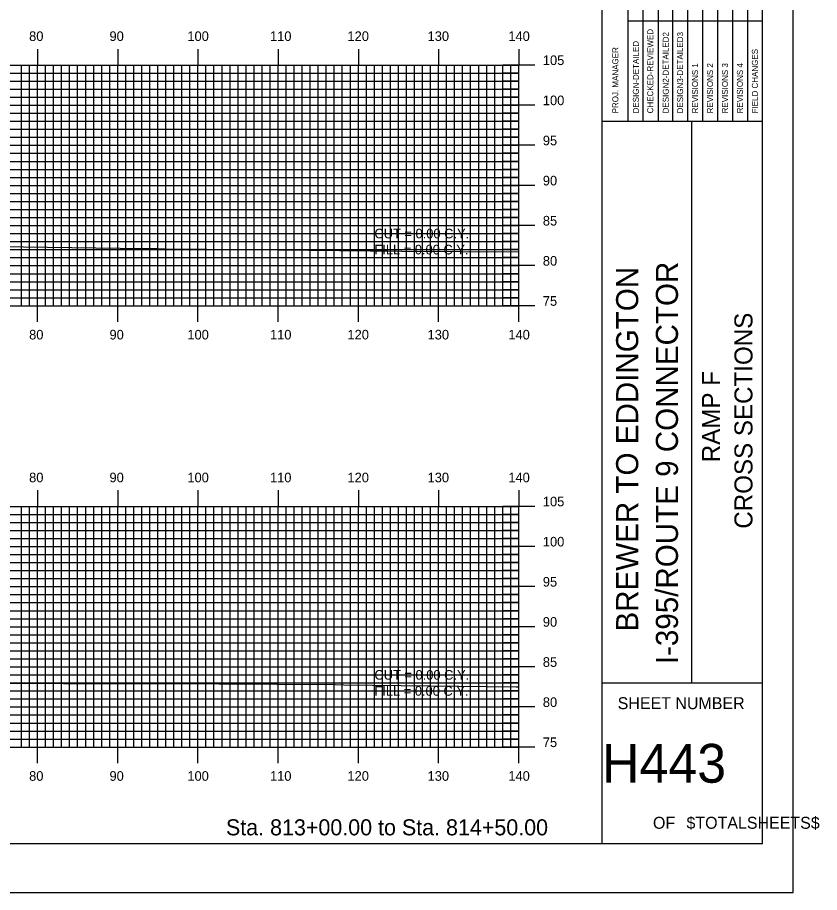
# Model space of a CAD drawing. Extents: x 2453 to 2796, y -1658 to -1438.
# Drawn here: x 2696.2 to 2796.2, y -1657.7 to -1548.7 of the extents above; entities that cross this region are included whole.
import ezdxf

# ---------------------------------------------------------------- set-up
doc = ezdxf.new("R2010")
doc.units = 0
for name, color, linetype in [('BORDER', 7, 'Continuous'), ('D_Text_Standard', 7, 'Continuous'), ('H_V ANNOTATION', 7, 'Continuous'), ('MAJOR', 7, 'Continuous'), ('MINOR', 7, 'Continuous'), ('PLOT BOUNDARY', 7, 'Continuous'), ('S_Roadway_Centerline', 7, 'Continuous')]:
    doc.layers.add(name, color=color, linetype=linetype)

msp = doc.modelspace()

# ---------------------------------------------------------------- linework, layer by layer
at = {"layer": 'BORDER'}
for p, q in [((2769.1, -1651.6), (2769.1, -1441.6)), ((2769.1, -1561.6), (2789.1, -1561.6)), ((2780.28, -1631.6), (2780.28, -1561.6)), ((2769.1, -1631.6), (2789.1, -1631.6))]:
    msp.add_line(p, q, dxfattribs=at)
msp.add_lwpolyline([(2469.1, -1651.6), (2789.1, -1651.6), (2789.1, -1441.6), (2469.1, -1441.6)], close=True, dxfattribs=at)
for points in [[(2774.19, -1561.59), (2774.19, -1526.6)], [(2776.06, -1526.6), (2776.06, -1561.59)], [(2777.92, -1561.59), (2777.92, -1526.6)], [(2779.78, -1561.59), (2779.78, -1526.6)], [(2781.65, -1561.59), (2781.65, -1526.6)], [(2783.51, -1561.59), (2783.51, -1526.6)], [(2785.37, -1561.59), (2785.37, -1526.6)], [(2787.24, -1561.59), (2787.24, -1526.6)], [(2772.33, -1561.59), (2772.33, -1528.01)], [(2772.33, -1549.1), (2789.1, -1549.1)]]:
    msp.add_lwpolyline(points, dxfattribs=at)
at = {"layer": 'MAJOR'}
for p, q in [((2698.7, -1552.6), (2698.7, -1554.6)), ((2708.7, -1552.6), (2708.7, -1554.6)), ((2718.7, -1552.6), (2718.7, -1554.6)), ((2728.7, -1552.6), (2728.7, -1554.6)), ((2738.7, -1552.6), (2738.7, -1554.6)), ((2748.7, -1552.6), (2748.7, -1554.6)), ((2758.7, -1552.6), (2758.7, -1554.6)), ((2478.7, -1554.6), (2758.7, -1554.6)), ((2478.7, -1554.6), (2758.7, -1554.6)), ((2698.7, -1584.6), (2698.7, -1554.6)), ((2708.7, -1584.6), (2708.7, -1554.6)), ((2718.7, -1584.6), (2718.7, -1554.6)), ((2728.7, -1584.6), (2728.7, -1554.6)), ((2738.7, -1584.6), (2738.7, -1554.6)), ((2748.7, -1584.6), (2748.7, -1554.6)), ((2760.7, -1554.6), (2756.7, -1554.6)), ((2758.7, -1584.6), (2758.7, -1554.6)), ((2758.7, -1584.6), (2758.7, -1554.6)), ((2478.7, -1559.6), (2758.7, -1559.6)), ((2760.7, -1559.6), (2756.7, -1559.6)), ((2478.7, -1564.6), (2758.7, -1564.6)), ((2760.7, -1564.6), (2756.7, -1564.6)), ((2478.7, -1569.6), (2758.7, -1569.6)), ((2760.7, -1569.6), (2756.7, -1569.6)), ((2478.7, -1574.6), (2758.7, -1574.6)), ((2760.7, -1574.6), (2756.7, -1574.6)), ((2478.7, -1579.6), (2758.7, -1579.6)), ((2760.7, -1579.6), (2756.7, -1579.6)), ((2478.7, -1584.6), (2758.7, -1584.6)), ((2478.7, -1584.6), (2758.7, -1584.6)), ((2698.7, -1586.61), (2698.7, -1584.6)), ((2708.7, -1586.61), (2708.7, -1584.6)), ((2718.7, -1586.61), (2718.7, -1584.6)), ((2728.7, -1586.61), (2728.7, -1584.6)), ((2738.7, -1586.61), (2738.7, -1584.6)), ((2748.7, -1586.61), (2748.7, -1584.6)), ((2760.7, -1584.6), (2756.7, -1584.6)), ((2758.7, -1586.61), (2758.7, -1584.6)), ((2698.7, -1607.6), (2698.7, -1609.6)), ((2708.7, -1607.6), (2708.7, -1609.6)), ((2718.7, -1607.6), (2718.7, -1609.6)), ((2728.7, -1607.6), (2728.7, -1609.6)), ((2738.7, -1607.6), (2738.7, -1609.6)), ((2748.7, -1607.6), (2748.7, -1609.6)), ((2758.7, -1607.6), (2758.7, -1609.6)), ((2478.7, -1609.6), (2758.7, -1609.6)), ((2478.7, -1609.6), (2758.7, -1609.6)), ((2698.7, -1639.6), (2698.7, -1609.6)), ((2708.7, -1639.6), (2708.7, -1609.6)), ((2718.7, -1639.6), (2718.7, -1609.6)), ((2728.7, -1639.6), (2728.7, -1609.6)), ((2738.7, -1639.6), (2738.7, -1609.6)), ((2748.7, -1639.6), (2748.7, -1609.6)), ((2760.7, -1609.6), (2756.7, -1609.6)), ((2758.7, -1639.6), (2758.7, -1609.6)), ((2758.7, -1639.6), (2758.7, -1609.6)), ((2478.7, -1614.6), (2758.7, -1614.6)), ((2760.7, -1614.6), (2756.7, -1614.6)), ((2478.7, -1619.6), (2758.7, -1619.6)), ((2760.7, -1619.6), (2756.7, -1619.6)), ((2478.7, -1624.6), (2758.7, -1624.6)), ((2760.7, -1624.6), (2756.7, -1624.6)), ((2478.7, -1629.6), (2758.7, -1629.6)), ((2760.7, -1629.6), (2756.7, -1629.6)), ((2478.7, -1634.6), (2758.7, -1634.6)), ((2760.7, -1634.6), (2756.7, -1634.6)), ((2478.7, -1639.6), (2758.7, -1639.6)), ((2478.7, -1639.6), (2758.7, -1639.6)), ((2698.7, -1641.61), (2698.7, -1639.6)), ((2708.7, -1641.61), (2708.7, -1639.6)), ((2718.7, -1641.61), (2718.7, -1639.6)), ((2728.7, -1641.61), (2728.7, -1639.6)), ((2738.7, -1641.61), (2738.7, -1639.6)), ((2748.7, -1641.61), (2748.7, -1639.6)), ((2760.7, -1639.6), (2756.7, -1639.6)), ((2758.7, -1641.61), (2758.7, -1639.6))]:
    msp.add_line(p, q, dxfattribs=at)
at = {"layer": 'MINOR'}
for p, q in [((2696.7, -1584.6), (2696.7, -1554.6)), ((2697.7, -1584.6), (2697.7, -1554.6)), ((2699.7, -1584.6), (2699.7, -1554.6)), ((2700.7, -1584.6), (2700.7, -1554.6)), ((2701.7, -1584.6), (2701.7, -1554.6)), ((2702.7, -1584.6), (2702.7, -1554.6)), ((2703.7, -1584.6), (2703.7, -1554.6)), ((2704.7, -1584.6), (2704.7, -1554.6)), ((2705.7, -1584.6), (2705.7, -1554.6)), ((2706.7, -1584.6), (2706.7, -1554.6)), ((2707.7, -1584.6), (2707.7, -1554.6)), ((2709.7, -1584.6), (2709.7, -1554.6)), ((2710.7, -1584.6), (2710.7, -1554.6)), ((2711.7, -1584.6), (2711.7, -1554.6)), ((2712.7, -1584.6), (2712.7, -1554.6)), ((2713.7, -1584.6), (2713.7, -1554.6)), ((2714.7, -1584.6), (2714.7, -1554.6)), ((2715.7, -1584.6), (2715.7, -1554.6)), ((2716.7, -1584.6), (2716.7, -1554.6)), ((2717.7, -1584.6), (2717.7, -1554.6)), ((2719.7, -1584.6), (2719.7, -1554.6)), ((2720.7, -1584.6), (2720.7, -1554.6)), ((2721.7, -1584.6), (2721.7, -1554.6)), ((2722.7, -1584.6), (2722.7, -1554.6)), ((2723.7, -1584.6), (2723.7, -1554.6)), ((2724.7, -1584.6), (2724.7, -1554.6)), ((2725.7, -1584.6), (2725.7, -1554.6)), ((2726.7, -1584.6), (2726.7, -1554.6)), ((2727.7, -1584.6), (2727.7, -1554.6)), ((2729.7, -1584.6), (2729.7, -1554.6)), ((2730.7, -1584.6), (2730.7, -1554.6)), ((2731.7, -1584.6), (2731.7, -1554.6)), ((2732.7, -1584.6), (2732.7, -1554.6)), ((2733.7, -1584.6), (2733.7, -1554.6)), ((2734.7, -1584.6), (2734.7, -1554.6)), ((2735.7, -1584.6), (2735.7, -1554.6)), ((2736.7, -1584.6), (2736.7, -1554.6)), ((2737.7, -1584.6), (2737.7, -1554.6)), ((2739.7, -1584.6), (2739.7, -1554.6)), ((2740.7, -1584.6), (2740.7, -1554.6)), ((2741.7, -1584.6), (2741.7, -1554.6)), ((2742.7, -1584.6), (2742.7, -1554.6)), ((2743.7, -1584.6), (2743.7, -1554.6)), ((2744.7, -1584.6), (2744.7, -1554.6)), ((2745.7, -1584.6), (2745.7, -1554.6)), ((2746.7, -1584.6), (2746.7, -1554.6)), ((2747.7, -1584.6), (2747.7, -1554.6)), ((2749.7, -1584.6), (2749.7, -1554.6)), ((2750.7, -1584.6), (2750.7, -1554.6)), ((2751.7, -1584.6), (2751.7, -1554.6)), ((2752.7, -1584.6), (2752.7, -1554.6)), ((2753.7, -1584.6), (2753.7, -1554.6)), ((2754.7, -1584.6), (2754.7, -1554.6)), ((2755.7, -1584.6), (2755.7, -1554.6)), ((2756.7, -1584.6), (2756.7, -1554.6)), ((2757.7, -1584.6), (2757.7, -1554.6)), ((2478.7, -1555.6), (2758.7, -1555.6)), ((2758.7, -1555.6), (2756.7, -1555.6)), ((2478.7, -1556.6), (2758.7, -1556.6)), ((2758.7, -1556.6), (2756.7, -1556.6)), ((2478.7, -1557.6), (2758.7, -1557.6)), ((2758.7, -1557.6), (2756.7, -1557.6)), ((2478.7, -1558.6), (2758.7, -1558.6)), ((2758.7, -1558.6), (2756.7, -1558.6)), ((2478.7, -1560.6), (2758.7, -1560.6)), ((2758.7, -1560.6), (2756.7, -1560.6)), ((2478.7, -1561.6), (2758.7, -1561.6)), ((2478.7, -1562.6), (2758.7, -1562.6)), ((2758.7, -1561.6), (2756.7, -1561.6)), ((2758.7, -1562.6), (2756.7, -1562.6)), ((2478.7, -1563.6), (2758.7, -1563.6)), ((2758.7, -1563.6), (2756.7, -1563.6)), ((2478.7, -1565.6), (2758.7, -1565.6)), ((2758.7, -1565.6), (2756.7, -1565.6)), ((2478.7, -1566.6), (2758.7, -1566.6)), ((2758.7, -1566.6), (2756.7, -1566.6)), ((2478.7, -1567.6), (2758.7, -1567.6)), ((2758.7, -1567.6), (2756.7, -1567.6)), ((2478.7, -1568.6), (2758.7, -1568.6)), ((2758.7, -1568.6), (2756.7, -1568.6)), ((2478.7, -1570.6), (2758.7, -1570.6)), ((2758.7, -1570.6), (2756.7, -1570.6)), ((2478.7, -1571.6), (2758.7, -1571.6)), ((2758.7, -1571.6), (2756.7, -1571.6)), ((2478.7, -1572.6), (2758.7, -1572.6)), ((2758.7, -1572.6), (2756.7, -1572.6)), ((2478.7, -1573.6), (2758.7, -1573.6)), ((2758.7, -1573.6), (2756.7, -1573.6)), ((2478.7, -1575.6), (2758.7, -1575.6)), ((2758.7, -1575.6), (2756.7, -1575.6)), ((2478.7, -1576.6), (2758.7, -1576.6)), ((2758.7, -1576.6), (2756.7, -1576.6)), ((2478.7, -1577.6), (2758.7, -1577.6)), ((2758.7, -1577.6), (2756.7, -1577.6)), ((2478.7, -1578.6), (2758.7, -1578.6)), ((2758.7, -1578.6), (2756.7, -1578.6)), ((2478.7, -1580.6), (2758.7, -1580.6)), ((2758.7, -1580.6), (2756.7, -1580.6)), ((2478.7, -1581.6), (2758.7, -1581.6)), ((2758.7, -1581.6), (2756.7, -1581.6)), ((2478.7, -1582.6), (2758.7, -1582.6)), ((2758.7, -1582.6), (2756.7, -1582.6)), ((2478.7, -1583.6), (2758.7, -1583.6)), ((2758.7, -1583.6), (2756.7, -1583.6)), ((2478.7, -1610.6), (2758.7, -1610.6)), ((2696.7, -1639.6), (2696.7, -1609.6)), ((2697.7, -1639.6), (2697.7, -1609.6)), ((2699.7, -1639.6), (2699.7, -1609.6)), ((2700.7, -1639.6), (2700.7, -1609.6)), ((2701.7, -1639.6), (2701.7, -1609.6)), ((2702.7, -1639.6), (2702.7, -1609.6)), ((2703.7, -1639.6), (2703.7, -1609.6)), ((2704.7, -1639.6), (2704.7, -1609.6)), ((2705.7, -1639.6), (2705.7, -1609.6)), ((2706.7, -1639.6), (2706.7, -1609.6)), ((2707.7, -1639.6), (2707.7, -1609.6)), ((2709.7, -1639.6), (2709.7, -1609.6)), ((2710.7, -1639.6), (2710.7, -1609.6)), ((2711.7, -1639.6), (2711.7, -1609.6)), ((2712.7, -1639.6), (2712.7, -1609.6)), ((2713.7, -1639.6), (2713.7, -1609.6)), ((2714.7, -1639.6), (2714.7, -1609.6)), ((2715.7, -1639.6), (2715.7, -1609.6)), ((2716.7, -1639.6), (2716.7, -1609.6)), ((2717.7, -1639.6), (2717.7, -1609.6)), ((2719.7, -1639.6), (2719.7, -1609.6)), ((2720.7, -1639.6), (2720.7, -1609.6)), ((2721.7, -1639.6), (2721.7, -1609.6)), ((2722.7, -1639.6), (2722.7, -1609.6)), ((2723.7, -1639.6), (2723.7, -1609.6)), ((2724.7, -1639.6), (2724.7, -1609.6)), ((2725.7, -1639.6), (2725.7, -1609.6)), ((2726.7, -1639.6), (2726.7, -1609.6)), ((2727.7, -1639.6), (2727.7, -1609.6)), ((2729.7, -1639.6), (2729.7, -1609.6)), ((2730.7, -1639.6), (2730.7, -1609.6)), ((2731.7, -1639.6), (2731.7, -1609.6)), ((2732.7, -1639.6), (2732.7, -1609.6)), ((2733.7, -1639.6), (2733.7, -1609.6)), ((2734.7, -1639.6), (2734.7, -1609.6)), ((2735.7, -1639.6), (2735.7, -1609.6)), ((2736.7, -1639.6), (2736.7, -1609.6)), ((2737.7, -1639.6), (2737.7, -1609.6)), ((2739.7, -1639.6), (2739.7, -1609.6)), ((2740.7, -1639.6), (2740.7, -1609.6)), ((2741.7, -1639.6), (2741.7, -1609.6)), ((2742.7, -1639.6), (2742.7, -1609.6)), ((2743.7, -1639.6), (2743.7, -1609.6)), ((2744.7, -1639.6), (2744.7, -1609.6)), ((2745.7, -1639.6), (2745.7, -1609.6)), ((2746.7, -1639.6), (2746.7, -1609.6)), ((2747.7, -1639.6), (2747.7, -1609.6)), ((2749.7, -1639.6), (2749.7, -1609.6)), ((2750.7, -1639.6), (2750.7, -1609.6)), ((2751.7, -1639.6), (2751.7, -1609.6)), ((2752.7, -1639.6), (2752.7, -1609.6)), ((2753.7, -1639.6), (2753.7, -1609.6)), ((2754.7, -1639.6), (2754.7, -1609.6)), ((2755.7, -1639.6), (2755.7, -1609.6)), ((2756.7, -1639.6), (2756.7, -1609.6)), ((2758.7, -1610.6), (2756.7, -1610.6)), ((2757.7, -1639.6), (2757.7, -1609.6)), ((2478.7, -1611.6), (2758.7, -1611.6)), ((2758.7, -1611.6), (2756.7, -1611.6)), ((2478.7, -1612.6), (2758.7, -1612.6)), ((2758.7, -1612.6), (2756.7, -1612.6)), ((2478.7, -1613.6), (2758.7, -1613.6)), ((2758.7, -1613.6), (2756.7, -1613.6)), ((2478.7, -1615.6), (2758.7, -1615.6)), ((2758.7, -1615.6), (2756.7, -1615.6)), ((2478.7, -1616.6), (2758.7, -1616.6)), ((2758.7, -1616.6), (2756.7, -1616.6)), ((2478.7, -1617.6), (2758.7, -1617.6)), ((2758.7, -1617.6), (2756.7, -1617.6)), ((2478.7, -1618.6), (2758.7, -1618.6)), ((2758.7, -1618.6), (2756.7, -1618.6)), ((2478.7, -1620.6), (2758.7, -1620.6)), ((2758.7, -1620.6), (2756.7, -1620.6)), ((2478.7, -1621.6), (2758.7, -1621.6)), ((2478.7, -1622.6), (2758.7, -1622.6)), ((2758.7, -1621.6), (2756.7, -1621.6)), ((2758.7, -1622.6), (2756.7, -1622.6)), ((2478.7, -1623.6), (2758.7, -1623.6)), ((2758.7, -1623.6), (2756.7, -1623.6)), ((2478.7, -1625.6), (2758.7, -1625.6)), ((2758.7, -1625.6), (2756.7, -1625.6)), ((2478.7, -1626.6), (2758.7, -1626.6)), ((2758.7, -1626.6), (2756.7, -1626.6)), ((2478.7, -1627.6), (2758.7, -1627.6)), ((2758.7, -1627.6), (2756.7, -1627.6)), ((2478.7, -1628.6), (2758.7, -1628.6)), ((2758.7, -1628.6), (2756.7, -1628.6)), ((2478.7, -1630.6), (2758.7, -1630.6)), ((2758.7, -1630.6), (2756.7, -1630.6)), ((2478.7, -1631.6), (2758.7, -1631.6)), ((2758.7, -1631.6), (2756.7, -1631.6)), ((2478.7, -1632.6), (2758.7, -1632.6)), ((2758.7, -1632.6), (2756.7, -1632.6)), ((2478.7, -1633.6), (2758.7, -1633.6)), ((2758.7, -1633.6), (2756.7, -1633.6)), ((2478.7, -1635.6), (2758.7, -1635.6)), ((2758.7, -1635.6), (2756.7, -1635.6)), ((2478.7, -1636.6), (2758.7, -1636.6)), ((2758.7, -1636.6), (2756.7, -1636.6)), ((2478.7, -1637.6), (2758.7, -1637.6)), ((2758.7, -1637.6), (2756.7, -1637.6)), ((2478.7, -1638.6), (2758.7, -1638.6)), ((2758.7, -1638.6), (2756.7, -1638.6))]:
    msp.add_line(p, q, dxfattribs=at)
at = {"layer": 'PLOT BOUNDARY'}
msp.add_lwpolyline([(2452.91, -1657.72), (2792.91, -1657.72), (2792.91, -1437.72), (2452.91, -1437.72)], close=True, dxfattribs=at)
at = {"layer": 'S_Roadway_Centerline'}
for points in [[(2687.09, -1577.17), (2696.94, -1577.25), (2712, -1577.45), (2713.38, -1577.46), (2713.59, -1577.45), (2713.72, -1577.49), (2714.72, -1577.49), (2724.89, -1577.57), (2740.16, -1577.76), (2742.36, -1577.77), (2744.11, -1577.79), (2758.7, -1577.86)], [(2596.6, -1629.72), (2597.11, -1629.73), (2606.94, -1630.07), (2619.82, -1630.58), (2621.49, -1630.63), (2642.62, -1631.03), (2644.61, -1631.03), (2655.37, -1631.01), (2666.35, -1631.05), (2667.2, -1631.04), (2668.06, -1631.07), (2688, -1631.59), (2689.21, -1631.6), (2690.55, -1631.63), (2701.95, -1631.69), (2712.5, -1631.68), (2714.02, -1631.66), (2735.8, -1631.82), (2736.87, -1631.83), (2758.39, -1632.07), (2758.7, -1632.08)]]:
    msp.add_lwpolyline(points, dxfattribs=at)

# ---------------------------------------------------------------- texts
at = {"layer": 'BORDER'}
for s, height, p in [('CHECKED-REVIEWED', 0.7455, (2775.46, -1560.62)), ('DESIGN2-DETAILED2', 0.7455, (2777.4, -1560.62)), ('DESIGN3-DETAILED3', 0.7455, (2779.19, -1560.62)), ('DESIGN-DETAILED', 0.7455, (2773.67, -1560.62)), ('PROJ. MANAGER', 0.7455, (2771.11, -1560.62)), ('FIELD CHANGES', 0.7455, (2788.51, -1560.62)), ('REVISIONS 1', 0.7455, (2781.05, -1560.62)), ('REVISIONS 2', 0.7455, (2782.92, -1560.62)), ('REVISIONS 3', 0.7455, (2784.78, -1560.62)), ('REVISIONS 4', 0.7455, (2786.64, -1560.62)), ('BREWER TO EDDINGTON', 2.7557, (2773.59, -1625.2)), ('I-395/ROUTE 9 CONNECTOR', 2.7557, (2778.55, -1629.27)), ('CROSS SECTIONS', 2.25, (2787.84, -1612.38)), ('RAMP F', 2.25, (2783.79, -1604.1))]:
    msp.add_text(s, height=height, rotation=90, dxfattribs=at).set_placement(p)
for s, height, p in [('SHEET NUMBER', 1.4905, (2771.03, -1634.87)), ('H443', 4.839, (2769.08, -1644.04)), ('OF', 1.491, (2775.43, -1649.78)), ('$TOTALSHEETS$', 1.4905, (2779.61, -1649.78))]:
    msp.add_text(s, height=height, dxfattribs=at).set_placement(p)
at = {"layer": 'D_Text_Standard'}
for s, p in [('CUT = 0.00 C.Y.', (2740.7, -1576.2)), ('FILL = 0.00 C.Y.', (2740.7, -1578.2)), ('CUT = 0.00 C.Y.', (2740.7, -1631.2)), ('FILL = 0.00 C.Y.', (2740.7, -1633.2))]:
    msp.add_text(s, height=1.2, dxfattribs=at).set_placement(p)
at = {"layer": 'H_V ANNOTATION'}
for s, height, p in [('80', 1.2, (2697.65, -1551.6)), ('90', 1.2, (2707.67, -1551.6)), ('100', 1.2, (2717.38, -1551.6)), ('110', 1.2, (2727.68, -1551.6)), ('120', 1.2, (2737.34, -1551.6)), ('130', 1.2, (2747.33, -1551.6)), ('140', 1.2, (2757.4, -1551.6)), ('105', 1.2, (2761.7, -1554.6)), ('100', 1.2, (2761.7, -1559.6)), ('95', 1.2, (2761.7, -1564.6)), ('90', 1.2, (2761.7, -1569.6)), ('85', 1.2, (2761.7, -1574.6)), ('80', 1.2, (2761.7, -1579.6)), ('75', 1.2, (2761.7, -1584.6)), ('80', 1.2, (2697.65, -1588.8)), ('90', 1.2, (2707.67, -1588.8)), ('100', 1.2, (2717.38, -1588.8)), ('110', 1.2, (2727.68, -1588.8)), ('120', 1.2, (2737.34, -1588.8)), ('130', 1.2, (2747.33, -1588.8)), ('140', 1.2, (2757.4, -1588.8)), ('80', 1.2, (2697.65, -1606.6)), ('90', 1.2, (2707.67, -1606.6)), ('100', 1.2, (2717.38, -1606.6)), ('110', 1.2, (2727.68, -1606.6)), ('120', 1.2, (2737.34, -1606.6)), ('130', 1.2, (2747.33, -1606.6)), ('140', 1.2, (2757.4, -1606.6)), ('105', 1.2, (2761.7, -1609.6)), ('100', 1.2, (2761.7, -1614.6)), ('95', 1.2, (2761.7, -1619.6)), ('90', 1.2, (2761.7, -1624.6)), ('85', 1.2, (2761.7, -1629.6)), ('80', 1.2, (2761.7, -1634.6)), ('75', 1.2, (2761.7, -1639.6)), ('80', 1.2, (2697.65, -1643.8)), ('90', 1.2, (2707.67, -1643.8)), ('100', 1.2, (2717.38, -1643.8)), ('110', 1.2, (2727.68, -1643.8)), ('120', 1.2, (2737.34, -1643.8)), ('130', 1.2, (2747.33, -1643.8)), ('140', 1.2, (2757.4, -1643.8)), ('Sta. 813+00.00 to Sta. 814+50.00', 2.0004, (2722.19, -1650.6))]:
    msp.add_text(s, height=height, dxfattribs=at).set_placement(p)

doc.saveas('drawing.dxf')
